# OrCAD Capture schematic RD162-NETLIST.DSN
size A3
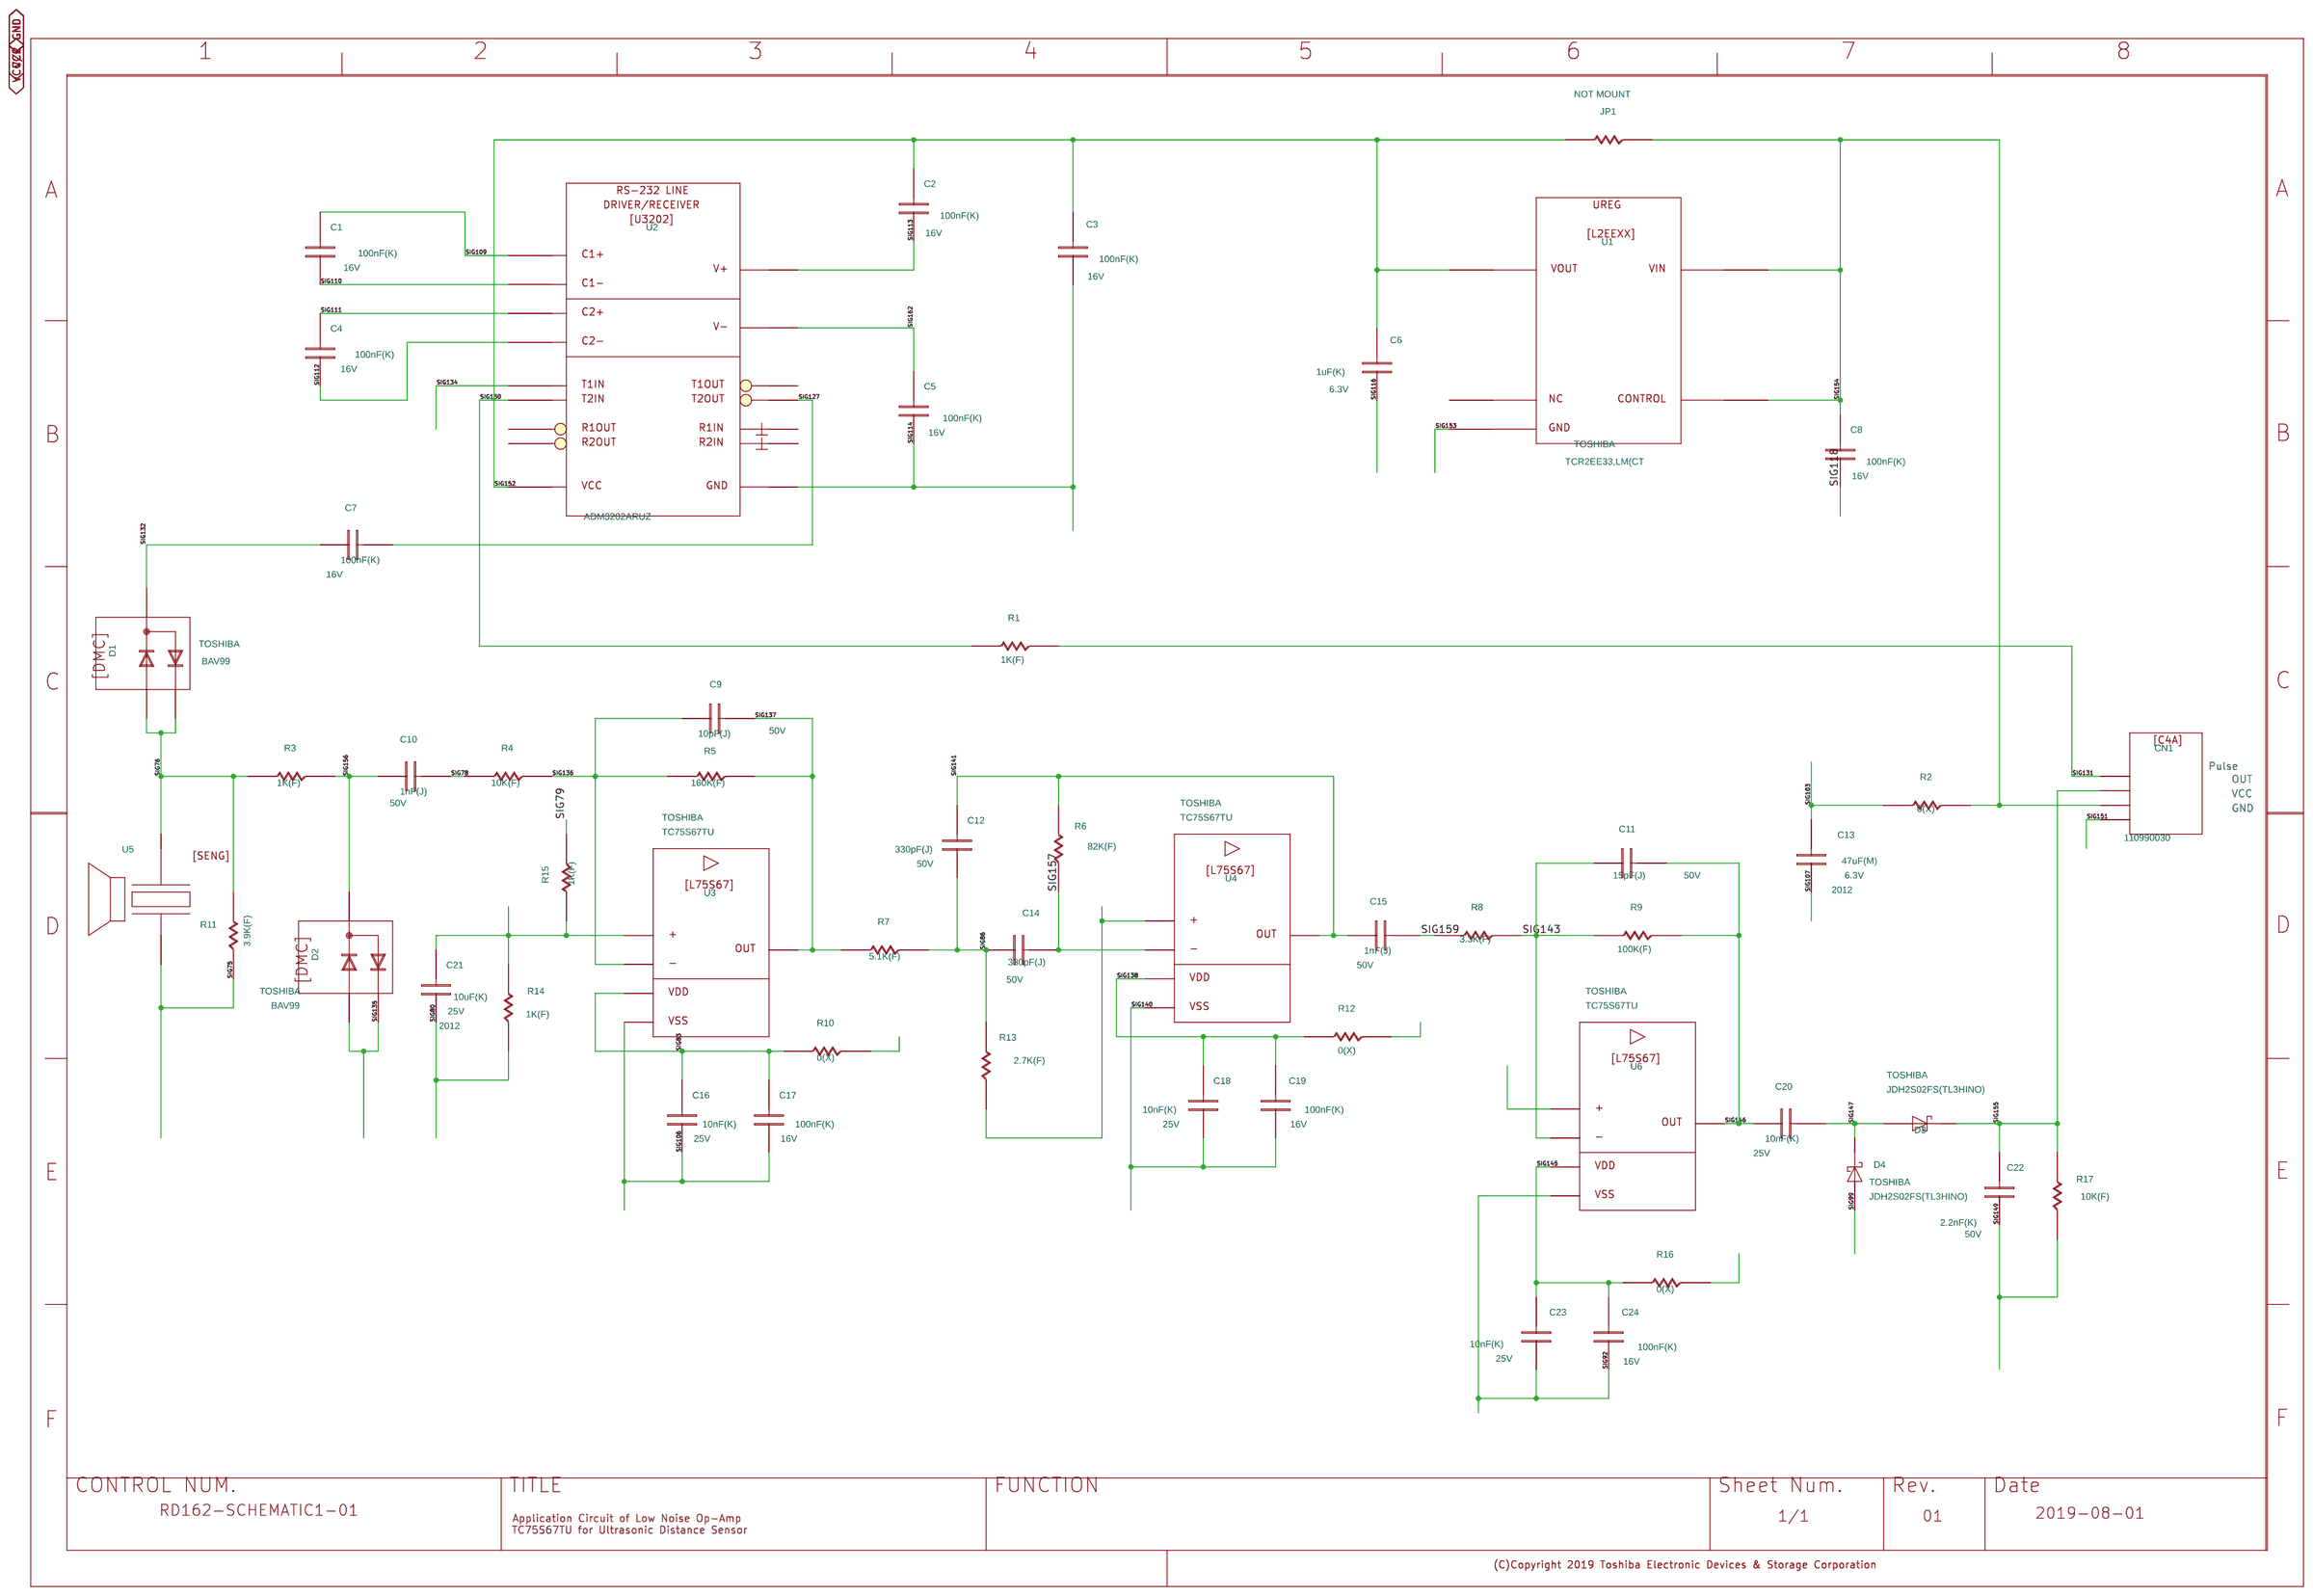
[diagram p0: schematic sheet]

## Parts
C1  C
C2  C
C3  C
C4  C
C5  C
C6  C
C7  C
C8  C
C9  C
C10  C
C11  C
C12  C
C13  C
C14  C
C15  C
C16  C
C17  C
C18  C
C19  C
C20  C
C21  C
C22  C
C23  C
C24  C
CN1  C4A
D1  DMC
D2  DMC
D3  SBD
D4  SBD
JP1  R
R1  R
R2  R
R3  R
R4  R
R5  R
R6  R
R7  R
R8  R
R9  R
R10  R
R11  R
R12  R
R13  R
R14  R
R15  R
R16  R
R17  R
U1  L2EEXX
U2  U3202
U3  L75S67
U4  L75S67
U5  SENG
U6  L75S67
U?#1  WAKU_DEF100

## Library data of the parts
C1-C5 C7 C8 C17 C19 C24 = C: CDBNAME: GDM030002515; COMPONENTNAME: GDM030002515_package; COMPONENTTYPE: 4; FUNCTION: GDM030002515; GCOUNT: 1; MAXGCOUNT: 1; PARTNAME: GDM030002515; SIZECODESMD: 1005; VAL1: 100nF(K); VAL2: 16V
C6 = C: CDBNAME: GDM030000207; COMPONENTNAME: GDM030000207_package; COMPONENTTYPE: 4; FUNCTION: GDM030000207; GCOUNT: 1; MAXGCOUNT: 1; PARTNAME: GDM030000207; SIZECODESMD: 1005; VAL1: 1uF(K); VAL2: 6.3V
C9 = C: CDBNAME: G36030133319; COMPONENTNAME: G36030133319_package; COMPONENTTYPE: 4; FUNCTION: G36030133319; GCOUNT: 1; MAXGCOUNT: 1; PARTNAME: G36030133319; SIZECODESMD: 1005; VAL1: 10pF(J); VAL2: 50V
C10 C15 = C: CDBNAME: GDM030002207; COMPONENTNAME: GDM030002207_package; COMPONENTTYPE: 4; FUNCTION: GDM030002207; GCOUNT: 1; MAXGCOUNT: 1; PARTNAME: GDM030002207; SIZECODESMD: 1005; VAL1: 1nF(J); VAL2: 50V
C11 = C: CDBNAME: G36030133067; COMPONENTNAME: G36030133067_package; COMPONENTTYPE: 4; FUNCTION: G36030133067; GCOUNT: 1; MAXGCOUNT: 1; PARTNAME: G36030133067; SIZECODESMD: 1005; VAL1: 15pF(J); VAL2: 50V
C12 C14 = C: CDBNAME: GAS030000198; COMPONENTNAME: GAS030000198_package; COMPONENTTYPE: 4; FUNCTION: GAS030000198; GCOUNT: 1; MAXGCOUNT: 1; PARTNAME: GAS030000198; SIZECODESMD: 1005; VAL1: 330pF(J); VAL2: 50V
C13 = C: CDBNAME: GDM030001363; COMPONENTNAME: GDM030001363_package; COMPONENTTYPE: 4; FUNCTION: GDM030001363; GCOUNT: 1; MAXGCOUNT: 1; PARTNAME: GDM030001363; SIZECODESMD: 2012; VAL1: 47uF(M); VAL2: 6.3V
C16 C18 C20 C23 = C: CDBNAME: GDM030002441; COMPONENTNAME: GDM030002441_package; COMPONENTTYPE: 4; FUNCTION: GDM030002441; GCOUNT: 1; MAXGCOUNT: 1; PARTNAME: GDM030002441; SIZECODESMD: 1005; VAL1: 10nF(K); VAL2: 25V
C21 = C: CDBNAME: GDM030002136; COMPONENTNAME: GDM030002136_package; COMPONENTTYPE: 4; FUNCTION: GDM030002136; GCOUNT: 1; MAXGCOUNT: 1; PARTNAME: GDM030002136; SIZECODESMD: 2012; VAL1: 10uF(K); VAL2: 25V
C22 = C: CDBNAME: G36030133234; COMPONENTNAME: G36030133234_package; COMPONENTTYPE: 4; FUNCTION: G36030133234; GCOUNT: 1; MAXGCOUNT: 1; PARTNAME: G36030133234; SIZECODESMD: 1005; VAL1: 2.2nF(K); VAL2: 50V
CN1 = C4A: CDBNAME: K22S001P; COMPONENTNAME: K22S001P_package; COMPONENTTYPE: 4; FUNCTION: K22S001P; GCOUNT: 1; MAXGCOUNT: 1; OUMEPARTTYPE: CN; PARTNAME: K22S001P; VAL3: 110990030
D1 D2 = DMC: CDBNAME: K4200526; COMPONENTNAME: K4200526_package; COMPONENTTYPE: 4; FUNCTION: K4200526; GCOUNT: 1; MAXGCOUNT: 1; OUMEPARTTYPE: D; PARTNAME: K4200526; USERCOMPTEXT3: TOSHIBA; VAL1: BAV99; VAL3: BAV99
D3 D4 = SBD: CDBNAME: GDM420000214; COMPONENTNAME: GDM420000214_package; COMPONENTTYPE: 4; FUNCTION: GDM420000214; GCOUNT: 1; MAXGCOUNT: 1; OUMEPARTTYPE: D; PARTNAME: GDM420000214; USERCOMPTEXT3: TOSHIBA; VAL1: JDH2S02FS(TL3HINO); VAL3: JDH2S02FS(TL3HINO)
JP1 = R: CDBNAME: GDM010002886; COMPONENTNAME: GDM010002886_package; COMPONENTTYPE: 4; FUNCTION: GDM010002886; GCOUNT: 1; MAXGCOUNT: 1; NOTMOUNT: NOT MOUNT; PARTNAME: GDM010002886; SIZECODESMD: 1005; VAL1: 0(X); VAL2: 63mW; VAL3: ERJ2GE0R00X
R1 R3 R14 R15 = R: CDBNAME: GDM010001350; COMPONENTNAME: GDM010001350_package; COMPONENTTYPE: 4; FUNCTION: GDM010001350; GCOUNT: 1; MAXGCOUNT: 1; PARTNAME: GDM010001350; SIZECODESMD: 1005; VAL1: 1K(F); VAL2: 100mW
R2 R10 R12 R16 = R: CDBNAME: GDM010002886; COMPONENTNAME: GDM010002886_package; COMPONENTTYPE: 4; FUNCTION: GDM010002886; GCOUNT: 1; MAXGCOUNT: 1; PARTNAME: GDM010002886; SIZECODESMD: 1005; VAL1: 0(X); VAL2: 1A
R4 R17 = R: CDBNAME: GDM010004244; COMPONENTNAME: GDM010004244_package; COMPONENTTYPE: 4; FUNCTION: GDM010004244; GCOUNT: 1; MAXGCOUNT: 1; PARTNAME: GDM010004244; SIZECODESMD: 1005; VAL1: 10K(F); VAL2: 100mW
R5 = R: CDBNAME: GDM010001678; COMPONENTNAME: GDM010001678_package; COMPONENTTYPE: 4; FUNCTION: GDM010001678; GCOUNT: 1; MAXGCOUNT: 1; PARTNAME: GDM010001678; SIZECODESMD: 1005; VAL1: 160K(F); VAL2: 100mW
R6 = R: CDBNAME: G36010118497; COMPONENTNAME: G36010118497_package; COMPONENTTYPE: 4; FUNCTION: G36010118497; GCOUNT: 1; MAXGCOUNT: 1; PARTNAME: G36010118497; SIZECODESMD: 1005; VAL1: 82K(F); VAL2: 100mW
R7 = R: CDBNAME: K0100567; COMPONENTNAME: K0100567_package; COMPONENTTYPE: 4; FUNCTION: K0100567; GCOUNT: 1; MAXGCOUNT: 1; PARTNAME: K0100567; SIZECODESMD: 1005; VAL1: 5.1K(F); VAL2: 100mW
R8 = R: CDBNAME: G36010118343; COMPONENTNAME: G36010118343_package; COMPONENTTYPE: 4; FUNCTION: G36010118343; GCOUNT: 1; MAXGCOUNT: 1; PARTNAME: G36010118343; SIZECODESMD: 1005; VAL1: 3.3K(F); VAL2: 100mW
R9 = R: CDBNAME: G36010118060; COMPONENTNAME: G36010118060_package; COMPONENTTYPE: 4; FUNCTION: G36010118060; GCOUNT: 1; MAXGCOUNT: 1; PARTNAME: G36010118060; SIZECODESMD: 1005; VAL1: 100K(F); VAL2: 100mW
R11 = R: CDBNAME: G36010118633; COMPONENTNAME: G36010118633_package; COMPONENTTYPE: 4; FUNCTION: G36010118633; GCOUNT: 1; MAXGCOUNT: 1; PARTNAME: G36010118633; SIZECODESMD: 1005; VAL1: 3.9K(F); VAL2: 100mW
R13 = R: CDBNAME: G36010118619; COMPONENTNAME: G36010118619_package; COMPONENTTYPE: 4; FUNCTION: G36010118619; GCOUNT: 1; MAXGCOUNT: 1; PARTNAME: G36010118619; SIZECODESMD: 1005; VAL1: 2.7K(F); VAL2: 100mW
U1 = L2EEXX: CDBNAME: GDM470001887; COMPONENTNAME: GDM470001887_package; COMPONENTTYPE: 4; FUNCTION: GDM470001887; GCOUNT: 1; MAXGCOUNT: 1; OUMEPARTTYPE: IC; PARTNAME: GDM470001887; USERCOMPTEXT3: TOSHIBA; VAL1: TCR2EE33,LM(CT; VAL3: TCR2EE33,LM(CT
U2 = U3202: CDBNAME: K47S002D; COMPONENTNAME: K47S002D_package; COMPONENTTYPE: 4; FUNCTION: K47S002D; GCOUNT: 1; MAXGCOUNT: 1; OUMEPARTTYPE: IC; PARTNAME: K47S002D; SAVEAREA0: -25428,-650,76285,64123; UPDATEDATE: 2008/08/18; UPDATETIME: 10:59:36; UPDATEUSER: 19910145; VAL1: ADM3202ARUZ; VAL3: ADM3202ARUZ
U3 U4 U6 = L75S67: CDBNAME: K47S002A; COMPONENTNAME: K47S002A_package; COMPONENTTYPE: 4; FUNCTION: K47S002A; GCOUNT: 1; MAXGCOUNT: 1; OUMEPARTTYPE: IC; PARTNAME: K47S002A; SAVEAREA0: -72307,-25685,103712,61936; UPDATEDATE: 2015/03/06; UPDATETIME: 13:02:06; UPDATEUSER: 19990028; USERCOMPTEXT3: TOSHIBA; VAL1: TC75S67TU; VAL3: TC75S67TU
U5 = SENG: CDBNAME: K30S0001; COMPONENTNAME: K30S0001_package; COMPONENTTYPE: 4; FUNCTION: K30S0001; GCOUNT: 1; MAXGCOUNT: 1; OUMEPARTTYPE: MT; PARTNAME: K30S0001; VAL3: C4016A1
U?#1 = WAKU_DEF100: COMPONENTTYPE: 2; DATE: 2019-08-01; DRAWINGNUMBER: RD162-SCHEMATIC1-01; FUNCTION: None; REVISION: 01; SHEETNUMBER: 1/1; TITLE: Application Circuit of Low Noise Op-Amp / TC75S67TU for Ultrasonic Distance Sensor; UPDATEDATE: 2019/08/22; UPDATETIME: 16:56:55; UPDATEUSER: cae

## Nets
GND: C3.1 C5.1 C6.1 C8.1 C13.1 C16.1 C17.1 C18.1 C19.1 C21.1 C22.1 C23.1 C24.1 CN1.4 D2.A D2.C D4.A R11.2 R14.2 R17.2 U1.2 U2.11 U2.15 U3.2 U4.2 U5.2 U6.2
VCC: C13.2 R2.1 R10.2 R12.2 R15.2 R16.2
SIG76: D1.A D1.C R3.1 R11.1 U5.1
SIG78: C10.2 R4.1
SIG83: C16.2 C17.2 R10.1 U3.5
SIG86: C12.1 C14.1 R7.2 R13.1
SIG109: C1.2 U2.1
SIG110: C1.1 U2.3
SIG111: C4.2 U2.4
SIG112: C4.1 U2.5
SIG113: C2.1 U2.2
SIG127: C7.2 U2.7
SIG130: R1.1 U2.10
SIG131: CN1.1 R1.2
SIG132: C7.1 D1.AC
SIG136: C9.1 R4.2 R5.1 U3.3
SIG137: C9.2 R5.2 R7.1 U3.4
SIG138: C18.2 C19.2 R12.1 U4.5
SIG141: C12.2 C15.1 R6.1 U4.4
SIG143: C11.1 R8.2 R9.1 U6.3
SIG145: C23.2 C24.2 R16.1 U6.5
SIG146: C11.2 C20.1 R9.2 U6.4
SIG147: C20.2 D3.A D4.C
SIG152: C2.2 C3.2 C6.2 JP1.1 U1.4 U2.16
SIG154: C8.2 CN1.3 JP1.2 R2.2 U1.1 U1.3
SIG155: C22.2 CN1.2 D3.C R17.1
SIG156: C10.1 D2.AC R3.2
SIG157: C14.2 R6.2 U4.3
SIG159: C15.2 R8.1
SIG162: C5.2 U2.6
VCC/2: C21.2 R13.2 R14.1 R15.1 U3.1 U4.1 U6.1

Not connected (* = marked no-connect by the designer): U1 5; U2 8 9 12 13 14

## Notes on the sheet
- Pulse
- OUT
- VCC
- GND
